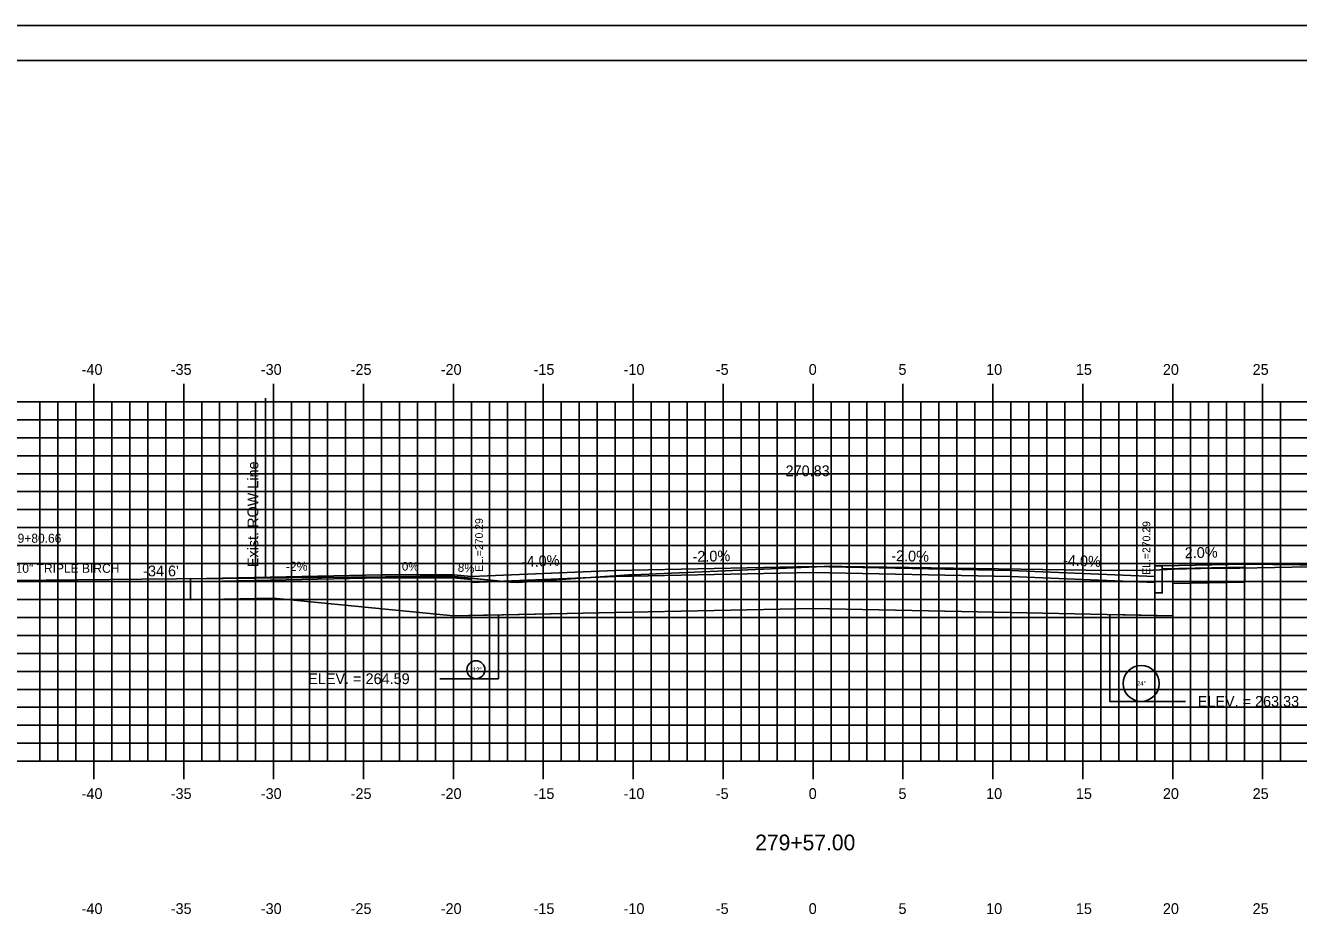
# Model space of a CAD drawing. Extents: x 854899 to 855069, y 366268 to 366378.
# Drawn here: x 854938 to 855008.8, y 366328.5 to 366378.2 of the extents above; entities that cross this region are included whole.
import ezdxf

# ---------------------------------------------------------------- set-up
doc = ezdxf.new("R2010")
doc.units = 0
for name, color, linetype in [('ANNOTATION', 7, 'Continuous'), ('BORDER', 7, 'Continuous'), ('D_Curb_Type_1_Rt', 7, 'Continuous'), ('D_Roadway_Centerline', 7, 'Continuous'), ('D_Roadway_Centerline_Text', 7, 'Continuous'), ('D_Roadway_Drive_Gravel_LT', 7, 'Continuous'), ('D_Roadway_Drive_Gravel_RT', 7, 'Continuous'), ('D_Roadway_Drive_SubGrade', 7, 'Continuous'), ('D_Roadway_Edge_Shoulder', 7, 'Continuous'), ('D_Roadway_FinishedGrade', 7, 'Continuous'), ('D_Roadway_Sidewalks_Paved', 7, 'Continuous'), ('D_Roadway_SubGrade', 7, 'Continuous'), ('D_Text_Monospaced', 7, 'Continuous'), ('D_Text_Standard', 7, 'Continuous'), ('E_ROW_Line', 7, 'Continuous'), ('H_V ANNOTATION', 7, 'Continuous'), ('JUNK COM EXC', 7, 'Continuous'), ('junk strct exc', 7, 'Continuous'), ('MAJOR', 7, 'Continuous'), ('MINOR', 7, 'Continuous'), ('PDRAIN', 7, 'Continuous'), ('PLOT BOUNDARY', 7, 'Continuous'), ('S_Roadway_Centerline', 7, 'Continuous')]:
    doc.layers.add(name, color=color, linetype=linetype)

msp = doc.modelspace()

# ---------------------------------------------------------------- linework, layer by layer
at = {"layer": 'BORDER'}
msp.add_line((855066.774, 366376.236), (854906.774, 366376.236), dxfattribs=at)
at = {"layer": 'D_Curb_Type_1_Rt'}
msp.add_lwpolyline([(855001.193, 366348.106), (855001.193, 366346.606), (855000.777, 366346.606), (855000.777, 366348.106)], close=True, dxfattribs=at)
at = {"layer": 'D_Roadway_Centerline'}
msp.add_lwpolyline([(854992.774, 366347.843), (855000.773, 366347.524), (855000.774, 366347.523)], dxfattribs=at)
at = {"layer": 'D_Roadway_Drive_Gravel_LT'}
for p, q in [((854961.774, 366347.603), (854957.774, 366347.603)), ((854962.774, 366347.523), (854961.774, 366347.603)), ((854961.767, 366347.437), (854957.774, 366347.437)), ((854962.774, 366347.356), (854961.767, 366347.437))]:
    msp.add_line(p, q, dxfattribs=at)
at = {"layer": 'D_Roadway_Drive_Gravel_RT'}
msp.add_line((855005.774, 366347.683), (855005.774, 366347.683), dxfattribs=at)
at = {"layer": 'D_Roadway_Drive_SubGrade'}
for p, q in [((854957.774, 366347.603), (854947.157, 366347.391)), ((854962.774, 366347.19), (854962.774, 366347.523)), ((854957.777, 366347.437), (854947.157, 366347.224)), ((854947.157, 366347.391), (854947.157, 366346.224)), ((854951.774, 366346.316), (854947.157, 366346.224)), ((854961.774, 366345.33), (854951.774, 366346.316)), ((854962.774, 366345.35), (854961.774, 366345.33)), ((855000.774, 366345.35), (855001.774, 366345.33))]:
    msp.add_line(p, q, dxfattribs=at)
at = {"layer": 'D_Roadway_Edge_Shoulder'}
msp.add_line((855000.774, 366347.523), (855000.774, 366347.19), dxfattribs=at)
msp.add_lwpolyline([(854962.774, 366347.523), (854970.774, 366347.843), (854981.774, 366348.063), (854992.774, 366347.843), (855000.774, 366347.523)], dxfattribs=at)
at = {"layer": 'D_Roadway_FinishedGrade'}
msp.add_line((855005.782, 366348.198), (855018.174, 366348.058), dxfattribs=at)
at = {"layer": 'D_Roadway_Sidewalks_Paved'}
msp.add_lwpolyline([(855001.194, 366348.106), (855005.782, 366348.198), (855005.782, 366348.031), (855001.194, 366347.939)], close=True, dxfattribs=at)
at = {"layer": 'D_Roadway_SubGrade'}
for points in [[(854970.774, 366347.51), (854962.774, 366347.19), (854962.774, 366345.35), (854970.774, 366345.51)], [(854970.774, 366345.51), (854970.774, 366347.51), (854981.774, 366347.73), (854992.774, 366347.51), (854992.774, 366345.51), (854981.774, 366345.73)], [(854992.774, 366347.51), (855000.774, 366347.19), (855000.774, 366345.35), (854992.774, 366345.51)]]:
    msp.add_lwpolyline(points, close=True, dxfattribs=at)
msp.add_lwpolyline([(855005.782, 366348.031), (855005.782, 366347.197), (855001.777, 366347.117), (855001.777, 366345.329), (855000.777, 366345.349)], dxfattribs=at)
at = {"layer": 'D_Text_Standard'}
for points in [[(854961.774, 366341.829), (854961.703, 366341.829), (854961.023, 366341.829)], [(855001.774, 366340.566), (855001.805, 366340.566), (855002.485, 366340.566)]]:
    msp.add_lwpolyline(points, dxfattribs=at)
at = {"layer": 'E_ROW_Line'}
msp.add_line((854951.323, 366347.433), (854951.323, 366357.433), dxfattribs=at)
at = {"layer": 'JUNK COM EXC'}
msp.add_lwpolyline([(854961.774, 366345.33), (854961.774, 366347.515), (854961.662, 366347.525), (854959.926, 366347.522), (854947.157, 366347.391), (854947.157, 366346.224), (854951.774, 366346.316), (854961.774, 366345.33)], dxfattribs=at)
msp.add_lwpolyline([(854961.774, 366347.515), (854961.774, 366345.33), (854970.774, 366345.51), (854981.774, 366345.73), (854992.774, 366345.51), (855000.774, 366345.35), (855001.774, 366345.33), (855001.777, 366347.117), (855005.782, 366347.197), (855005.774, 366347.991), (855004.079, 366347.978), (855001.774, 366347.926), (855000.308, 366347.852), (854996.962, 366347.86), (854993.304, 366347.931), (854983.385, 366348.065), (854982.395, 366348.069), (854971.79, 366347.613), (854971.53, 366347.601), (854971.014, 366347.57), (854965.329, 366347.182), (854964.949, 366347.208)], close=True, dxfattribs=at)
at = {"layer": 'junk strct exc'}
for points in [[(854961.774, 366345.33), (854961.774, 366341.829), (854964.274, 366341.829), (854964.274, 366345.38)], [(854998.274, 366345.4), (854998.274, 366340.566), (855001.774, 366340.566), (855001.774, 366345.33)]]:
    msp.add_lwpolyline(points, close=True, dxfattribs=at)
at = {"layer": 'MAJOR'}
for p, q in [((854941.774, 366358.238), (854941.774, 366357.236)), ((854946.774, 366358.238), (854946.774, 366357.236)), ((854951.774, 366358.238), (854951.774, 366357.236)), ((854956.774, 366358.238), (854956.774, 366357.236)), ((854961.774, 366358.238), (854961.774, 366357.236)), ((854966.774, 366358.238), (854966.774, 366357.236)), ((854971.774, 366358.238), (854971.774, 366357.236)), ((854976.774, 366358.238), (854976.774, 366357.236)), ((854981.774, 366358.238), (854981.774, 366357.236)), ((854986.774, 366358.238), (854986.774, 366357.236)), ((854991.774, 366358.238), (854991.774, 366357.236)), ((854996.774, 366358.238), (854996.774, 366357.236)), ((855001.774, 366358.238), (855001.774, 366357.236)), ((855006.774, 366358.238), (855006.774, 366357.236)), ((854911.774, 366357.236), (855051.774, 366357.236)), ((854911.774, 366357.236), (855051.774, 366357.236)), ((854941.774, 366337.236), (854941.774, 366357.236)), ((854946.774, 366337.236), (854946.774, 366357.236)), ((854951.774, 366337.236), (854951.774, 366357.236)), ((854956.774, 366337.236), (854956.774, 366357.236)), ((854961.774, 366337.236), (854961.774, 366357.236)), ((854966.774, 366337.236), (854966.774, 366357.236)), ((854971.774, 366337.236), (854971.774, 366357.236)), ((854976.774, 366337.236), (854976.774, 366357.236)), ((854981.774, 366337.236), (854981.774, 366357.236)), ((854986.774, 366337.236), (854986.774, 366357.236)), ((854991.774, 366337.236), (854991.774, 366357.236)), ((854996.774, 366337.236), (854996.774, 366357.236)), ((855001.774, 366337.236), (855001.774, 366357.236)), ((855006.774, 366337.236), (855006.774, 366357.236)), ((854911.774, 366352.236), (855051.774, 366352.236)), ((854911.774, 366347.236), (855051.774, 366347.236)), ((854911.774, 366342.236), (855051.774, 366342.236)), ((854911.774, 366337.236), (855051.774, 366337.236)), ((854911.774, 366337.236), (855051.774, 366337.236)), ((854941.774, 366336.234), (854941.774, 366337.236)), ((854946.774, 366336.234), (854946.774, 366337.236)), ((854951.774, 366336.234), (854951.774, 366337.236)), ((854956.774, 366336.234), (854956.774, 366337.236)), ((854961.774, 366336.234), (854961.774, 366337.236)), ((854966.774, 366336.234), (854966.774, 366337.236)), ((854971.774, 366336.234), (854971.774, 366337.236)), ((854976.774, 366336.234), (854976.774, 366337.236)), ((854981.774, 366336.234), (854981.774, 366337.236)), ((854986.774, 366336.234), (854986.774, 366337.236)), ((854991.774, 366336.234), (854991.774, 366337.236)), ((854996.774, 366336.234), (854996.774, 366337.236)), ((855001.774, 366336.234), (855001.774, 366337.236)), ((855006.774, 366336.234), (855006.774, 366337.236))]:
    msp.add_line(p, q, dxfattribs=at)
at = {"layer": 'MINOR'}
for p, q in [((854938.774, 366337.236), (854938.774, 366357.236)), ((854939.774, 366337.236), (854939.774, 366357.236)), ((854940.774, 366337.236), (854940.774, 366357.236)), ((854942.774, 366337.236), (854942.774, 366357.236)), ((854943.774, 366337.236), (854943.774, 366357.236)), ((854944.774, 366337.236), (854944.774, 366357.236)), ((854945.774, 366337.236), (854945.774, 366357.236)), ((854947.774, 366337.236), (854947.774, 366357.236)), ((854948.774, 366337.236), (854948.774, 366357.236)), ((854949.774, 366337.236), (854949.774, 366357.236)), ((854950.774, 366337.236), (854950.774, 366357.236)), ((854952.774, 366337.236), (854952.774, 366357.236)), ((854953.774, 366337.236), (854953.774, 366357.236)), ((854954.774, 366337.236), (854954.774, 366357.236)), ((854955.774, 366337.236), (854955.774, 366357.236)), ((854957.774, 366337.236), (854957.774, 366357.236)), ((854958.774, 366337.236), (854958.774, 366357.236)), ((854959.774, 366337.236), (854959.774, 366357.236)), ((854960.774, 366337.236), (854960.774, 366357.236)), ((854962.774, 366337.236), (854962.774, 366357.236)), ((854963.774, 366337.236), (854963.774, 366357.236)), ((854964.774, 366337.236), (854964.774, 366357.236)), ((854965.774, 366337.236), (854965.774, 366357.236)), ((854967.774, 366337.236), (854967.774, 366357.236)), ((854968.774, 366337.236), (854968.774, 366357.236)), ((854969.774, 366337.236), (854969.774, 366357.236)), ((854970.774, 366337.236), (854970.774, 366357.236)), ((854972.774, 366337.236), (854972.774, 366357.236)), ((854973.774, 366337.236), (854973.774, 366357.236)), ((854974.774, 366337.236), (854974.774, 366357.236)), ((854975.774, 366337.236), (854975.774, 366357.236)), ((854977.774, 366337.236), (854977.774, 366357.236)), ((854978.774, 366337.236), (854978.774, 366357.236)), ((854979.774, 366337.236), (854979.774, 366357.236)), ((854980.774, 366337.236), (854980.774, 366357.236)), ((854982.774, 366337.236), (854982.774, 366357.236)), ((854983.774, 366337.236), (854983.774, 366357.236)), ((854984.774, 366337.236), (854984.774, 366357.236)), ((854985.774, 366337.236), (854985.774, 366357.236)), ((854987.774, 366337.236), (854987.774, 366357.236)), ((854988.774, 366337.236), (854988.774, 366357.236)), ((854989.774, 366337.236), (854989.774, 366357.236)), ((854990.774, 366337.236), (854990.774, 366357.236)), ((854992.774, 366337.236), (854992.774, 366357.236)), ((854993.774, 366337.236), (854993.774, 366357.236)), ((854994.774, 366337.236), (854994.774, 366357.236)), ((854995.774, 366337.236), (854995.774, 366357.236)), ((854997.774, 366337.236), (854997.774, 366357.236)), ((854998.774, 366337.236), (854998.774, 366357.236)), ((854999.774, 366337.236), (854999.774, 366357.236)), ((855000.774, 366337.236), (855000.774, 366357.236)), ((855002.774, 366337.236), (855002.774, 366357.236)), ((855003.774, 366337.236), (855003.774, 366357.236)), ((855004.774, 366337.236), (855004.774, 366357.236)), ((855005.774, 366337.236), (855005.774, 366357.236)), ((855007.774, 366337.236), (855007.774, 366357.236)), ((854911.774, 366356.236), (855051.774, 366356.236)), ((854911.774, 366355.236), (855051.774, 366355.236)), ((854911.774, 366354.236), (855051.774, 366354.236)), ((854911.774, 366353.236), (855051.774, 366353.236)), ((854911.774, 366351.236), (855051.774, 366351.236)), ((854911.774, 366350.236), (855051.774, 366350.236)), ((854911.774, 366349.236), (855051.774, 366349.236)), ((854911.774, 366348.236), (855051.774, 366348.236)), ((854911.774, 366346.236), (855051.774, 366346.236)), ((854911.774, 366345.236), (855051.774, 366345.236)), ((854911.774, 366344.236), (855051.774, 366344.236)), ((854911.774, 366343.236), (855051.774, 366343.236)), ((854911.774, 366341.236), (855051.774, 366341.236)), ((854911.774, 366340.236), (855051.774, 366340.236)), ((854911.774, 366339.236), (855051.774, 366339.236)), ((854911.774, 366338.236), (855051.774, 366338.236))]:
    msp.add_line(p, q, dxfattribs=at)
at = {"layer": 'PDRAIN'}
for points in [[(854998.274, 366345.4), (854998.274, 366340.566), (855001.774, 366340.566), (855001.774, 366345.33)], [(854961.774, 366345.33), (854961.774, 366341.829), (854964.274, 366341.829), (854964.274, 366345.33)]]:
    msp.add_lwpolyline(points, dxfattribs=at)
for centre, radius in [((854963.024, 366342.329), 0.5), ((855000.024, 366341.566), 1)]:
    msp.add_circle(centre, radius, dxfattribs=at)
at = {"layer": 'PLOT BOUNDARY'}
msp.add_lwpolyline([(854898.681, 366268.177), (855068.681, 366268.177), (855068.681, 366378.177), (854898.681, 366378.177)], close=True, dxfattribs=at)
at = {"layer": 'S_Roadway_Centerline'}
msp.add_lwpolyline([(854922.581, 366346.808), (854933.213, 366347.24), (854933.77, 366347.25), (854944.438, 366347.363), (854959.926, 366347.522), (854961.662, 366347.525), (854964.949, 366347.208), (854965.329, 366347.182), (854971.014, 366347.57), (854971.53, 366347.601), (854971.79, 366347.613), (854982.395, 366348.069), (854983.385, 366348.065), (854993.304, 366347.931), (854996.962, 366347.86), (855000.308, 366347.852), (855002.655, 366347.97), (855005.503, 366347.986), (855011.351, 366348.088)], dxfattribs=at)

# ---------------------------------------------------------------- texts
at = {"layer": 'ANNOTATION'}
for s, height, rotation, p in [('-2.0%', 0.6, 1.14576, (854975.077, 366348.33)), ('-2.0%', 0.6, 358.85424, (854986.117, 366348.377)), ('2.0%', 0.6, 1.14846, (855002.45, 366348.531)), ('-2%', 0.51, 1.14576, (854952.455, 366347.813)), ('-4.0%', 0.6, 2.29061, (854965.59, 366348.037)), ('-4.0%', 0.6, 357.70947, (854995.669, 366348.128))]:
    msp.add_text(s, height=height, rotation=rotation, dxfattribs=at).set_placement(p)
at = {"layer": 'D_Roadway_Centerline_Text'}
msp.add_text('270.83', height=0.6, dxfattribs=at).set_placement((854980.246, 366353.095))
at = {"layer": 'D_Roadway_Drive_Gravel_LT'}
msp.add_text('0%', height=0.48, dxfattribs=at).set_placement((854958.91, 366347.843))
msp.add_text('8%', height=0.48, rotation=355.42608, dxfattribs=at).set_placement((854962.005, 366347.79))
at = {"layer": 'D_Text_Monospaced'}
for s, p in [('STA. 279+80.66', (854935.123, 366349.394)), ('EXIST. 10" TRIPLE BIRCH', (854935.123, 366347.72))]:
    msp.add_text(s, height=0.49998, dxfattribs=at).set_placement(p)
at = {"layer": 'D_Text_Standard'}
for p in [(854963.418, 366347.617), (855000.529, 366347.454)]:
    msp.add_text(' EL.=270.29', height=0.4335, rotation=90, dxfattribs=at).set_placement(p)
for s, p in [("-34.6'", (854944.52, 366347.525)), ('ELEV. = 264.59', (854953.698, 366341.529)), ('ELEV. = 263.33', (855003.165, 366340.266))]:
    msp.add_text(s, height=0.6, dxfattribs=at).set_placement(p)
at = {"layer": 'E_ROW_Line'}
msp.add_text('Exist. ROW Line', height=0.6, rotation=90, dxfattribs=at).set_placement((854950.923, 366348.033))
at = {"layer": 'H_V ANNOTATION'}
for s, height, p in [('-40', 0.6, (854941.1, 366358.736)), ('-35', 0.6, (854946.054, 366358.736)), ('-30', 0.6, (854951.062, 366358.736)), ('-25', 0.6, (854956.06, 366358.736)), ('-20', 0.6, (854961.068, 366358.736)), ('-15', 0.6, (854966.231, 366358.736)), ('-10', 0.6, (854971.239, 366358.736)), ('-5', 0.6, (854976.365, 366358.736)), ('0', 0.6, (854981.533, 366358.736)), ('5', 0.6, (854986.525, 366358.736)), ('10', 0.6, (854991.399, 366358.736)), ('15', 0.6, (854996.391, 366358.736)), ('20', 0.6, (855001.228, 366358.736)), ('25', 0.6, (855006.22, 366358.736)), ('-40', 0.6, (854941.1, 366335.136)), ('-35', 0.6, (854946.054, 366335.136)), ('-30', 0.6, (854951.062, 366335.136)), ('-25', 0.6, (854956.06, 366335.136)), ('-20', 0.6, (854961.068, 366335.136)), ('-15', 0.6, (854966.231, 366335.136)), ('-10', 0.6, (854971.239, 366335.136)), ('-5', 0.6, (854976.365, 366335.136)), ('0', 0.6, (854981.533, 366335.136)), ('5', 0.6, (854986.525, 366335.136)), ('10', 0.6, (854991.399, 366335.136)), ('15', 0.6, (854996.391, 366335.136)), ('20', 0.6, (855001.228, 366335.136)), ('25', 0.6, (855006.22, 366335.136)), ('279+57.00', 0.875, (854978.559, 366332.28)), ('-40', 0.6, (854941.1, 366328.736)), ('-35', 0.6, (854946.054, 366328.736)), ('-30', 0.6, (854951.062, 366328.736)), ('-25', 0.6, (854956.06, 366328.736)), ('-20', 0.6, (854961.068, 366328.736)), ('-15', 0.6, (854966.231, 366328.736)), ('-10', 0.6, (854971.239, 366328.736)), ('-5', 0.6, (854976.365, 366328.736)), ('0', 0.6, (854981.533, 366328.736)), ('5', 0.6, (854986.525, 366328.736)), ('10', 0.6, (854991.399, 366328.736)), ('15', 0.6, (854996.391, 366328.736)), ('20', 0.6, (855001.228, 366328.736)), ('25', 0.6, (855006.22, 366328.736))]:
    msp.add_text(s, height=height, dxfattribs=at).set_placement(p)
at = {"layer": 'PDRAIN'}
for s, p in [('12"', (854962.833, 366342.204)), ('24"', (854999.782, 366341.441))]:
    msp.add_text(s, height=0.25, dxfattribs=at).set_placement(p)
at = {"layer": 'S_Roadway_Centerline'}
for s, p in [('C', (854982.39, 366348.069)), ('L', (854982.395, 366348.062))]:
    msp.add_text(s, height=0.0146, dxfattribs=at).set_placement(p)

doc.saveas('drawing.dxf')
